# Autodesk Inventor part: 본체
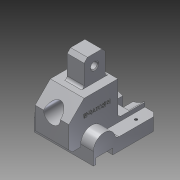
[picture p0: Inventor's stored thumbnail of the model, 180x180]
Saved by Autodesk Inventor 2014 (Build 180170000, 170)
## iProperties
Created: 2016-11
Part Number: 본체
Material: 알루미늄 6061
Document SubType Name: Modeling
Designer: USER
Density: 2.71 g/cm^3
Appearance: 알루미늄 - 평지
Mass: 462.906 g
Surface Area: 317.29 cm^2
Volume: 170.814 cm^3
Author: USER
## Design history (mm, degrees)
sketch "스케치1"
  geometry: L1 (63, 0)-(63, -15); L2 (63, -15)-(10, -15); L3 (10, -15)-(10, -8); L4 (10, -8)-(-10, -8); L5 (-10, -8)-(-10, -15); L6 (-10, -15)-(-13, -15); L7 (-13, -15)-(-13, 0); L8 (13, 0)-(63, 0); A1 r 13 centre (0, 0) between (13, 0) and (-13, 0); 1 further point
  constraints: 16 end point, 3 horizontal alignment, 3 parallel, 2 point on circle, 2 vertical alignment, 1 centre point, 1 coincident, 1 perpendicular, 1 tangent
  dimensions: "d1" = 26 diameter of A1; "d2" = 3 distance of L5.end L6.end; "d3" = 20 distance of L3.end L4.end; "d4" = 7 distance between parallel lines of L6 L4; "d5" = 63 distance from line of L1 point (0, 0); "d6" = 15 distance between parallel lines of L8 L2
extrude "돌출1" new body sketch "스케치1" stored distance "d7" = 70; taper "d8" = 0 deg
sketch "스케치2"
  geometry: L1 (63, -3)-(-27, -3); L2 (-27, -3)-(-27, 27); L3 (-27, 27)-(-9, 45); L4 (-9, 45)-(31, 45); L5 (31, 45)-(31, 5); L6 (31, 5)-(63, 5); L7 (63, 5)-(63, -3); L8 (63, -15)-(10, -15) reference; L9 (63, 0)-(63, -15) reference; L10 (-10, -15)-(-13, -15) reference; 1 further point
  constraints: 14 end point, 3 parallel, 2 vertical alignment, 1 horizontal, 1 perpendicular
  dimensions: "d9" = 48 distance between parallel lines of L4 L1; "d10" = 20 distance between parallel lines of L8 L6; "d11" = 45 deg angle of L4 L3; "d12" = 30 distance of L1.end L2.end; "d13" = 60 distance between parallel lines of L4 L10; "d14" = 58 distance between parallel lines of L5 L2; "d15" = 90 distance between parallel lines of L9 L2
extrude "돌출2" join sketch "스케치2" stored distance "d16" = 40; taper "d17" = 0 deg
sketch "스케치3"
  geometry: L1 (1, 41.207)-(26, 41.207); L2 (26, 41.207)-(26, 75); L3 (26, 75)-(1, 75); L4 (1, 75)-(1, 41.207); L5 (31, 45)-(31, 5) reference; L6 (63, -15)-(10, -15) reference; 1 further point
  constraints: 8 end point, 2 parallel, 1 horizontal, 1 perpendicular
  dimensions: "d18" = 25 distance of L2.end L3.end; "d19" = 5 distance between parallel lines of L5 L2; "d20" = 90 distance between parallel lines of L6 L3; "d21" = 33.79302 distance of L3.end L1.start
extrude "돌출3" join sketch "스케치3" stored distance "d22" = 20; taper "d23" = 0 deg
sketch "스케치5"
  geometry: L1 (55, 60)-(-15, 60) reference; 2 further points
  constraints: 1 vertical alignment
  dimensions: "d26" = 42 distance from line of L1 point (20, 18)
hole "구멍1" sketch "스케치5" at (20, 18) diameter "d27" = 20; stored, may be unused: countersink angle "d31" = 90 deg, drill point angle "d33" = 118 deg; dims "d28" = 6, "d29" = 29, "d30" = 7, "d32" = 8
sketch "스케치7"
  geometry: L1 (-75, 1)-(-45, 1) reference; L2 (-41.5, 31)-(-12.5, 31) reference; L3 (15, 63)-(15, 10) reference; C1 r 4 at (-62, 13.5); 1 further point
  constraints: 1 centre point
  dimensions: "d34" = 8 diameter of C1; "d35" = 12.5 distance from line of C1.centre L1; "d36" = 77 distance from line of L3 C1.centre
extrude "돌출4" cut sketch "스케치7" stored distance "d37" = 10; taper "d38" = 0 deg
sketch "스케치8"
  geometry: L1 (55, -20)-(15, -20) reference; L2 (41, 0)-(29, 0); L3 (29, 0)-(29, -13.627); L4 (41, -13.627)-(41, 0); C1 r 10 at (35, -42) reference; A1 r 29 centre (35, -42) between (53.894, -20) and (41, -13.627); A2 r 29 centre (35, -42) between (29, -13.627) and (16.106, -20); 3 further points
  constraints: 6 end point, 4 point on circle, 2 centre point, 2 point on line, 1 coincident, 1 horizontal, 1 horizontal alignment, 1 midpoint, 1 parallel, 1 perpendicular, 1 vertical alignment
  dimensions: "d40" = 12 distance of L2.start L2.end; "d41" = 29 radius of A1; "d42" = 29 radius of A2
extrude "돌출5" cut sketch "스케치8" distance "d43" = 18; taper "d44" = 0 deg
fillet "모깎기1" dims "d45" = 5
chamfer "모따기1" distance "d46" = 4; stored, may be unused: second distance "d47" = 2, angle "d48" = 45 deg
chamfer "모따기2" distance "d49" = 1; stored, may be unused: second distance "d50" = 2, angle "d51" = 45 deg
sketch "스케치9"
  geometry: L1 (0, 0)-(15, 0) reference; L2 (-14, -18)-(-14, 0) reference; L3 (15, 0)-(-14, 0) reference; L4 (15, -53)-(15, 0) reference; L5 (15, -53)-(-55, -53) reference; L6 (-55, 0)-(-55, -53) reference; L7 (-26, 0)-(-55, 0) reference; L8 (-26, 0)-(-26, -18) reference; L9 (-26, -18)-(-14, -18) reference; 3 further points
  dimensions: "d52" = 18 distance from line of L1 point (7.5, -18); "d53" = 18 distance from line of point (-47.5, -18) L7; "d54" = 55 distance of point (7.5, -18) point (-47.5, -18); "d55" = 7.5 distance from line of L6 point (-47.5, -18)
hole "구멍2" sketch "스케치9" at (7.5, -18), (-47.5, -18) diameter "d56" = 3.242; stored, may be unused: countersink angle "d60" = 90 deg, drill point angle "d62" = 118 deg; dims "d57" = 6, "d58" = 29, "d59" = 7, "d61" = 8
chamfer "모따기3" distance "d63" = 5; stored, may be unused: second distance "d64" = 2, angle "d65" = 45 deg
sketch "스케치10"
  geometry: L1 (-5, 31)-(-45, 31) reference; L2 (-45, 31)-(-45, -9) reference; 1 further point
  constraints: 1 other
  dimensions: "d66" = 25 distance from line of point (-27, 6) L1; "d67" = 18 distance from line of point (-27, 6) L2
feature "엠보싱1" sketch "스케치10" dims "d68" = 0.5, "d69" = 0
fillet "모깎기2" dims "d70" = 3
node "솔리드1"
node "투영된 루프1"
other parameters: "d39" = 58
